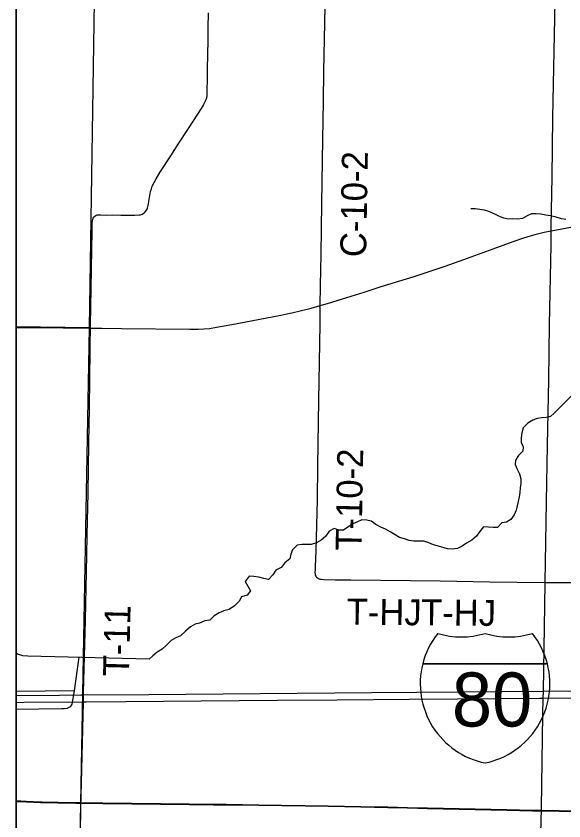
# Model space of a CAD drawing. Extents: x -21.7 to 34, y 0 to 22.
# Drawn here: x 23.517 to 24.718, y 18.47 to 20.235 of the extents above; entities that cross this region are included whole.
import ezdxf

# ---------------------------------------------------------------- set-up
doc = ezdxf.new("R2010")
doc.units = 0
for name, color, linetype in [('Default', 7, 'Continuous'), ('GM_X_County_Road', 7, 'Continuous'), ('GM_X_County_Road_Text', 7, 'Continuous'), ('GM_X_Interchange_Ramps', 7, 'Continuous'), ('GM_X_Interstate_Location', 7, 'Continuous'), ('GM_X_Interstate_Route', 7, 'Continuous'), ('GM_X_Interstate_Shield', 7, 'Continuous'), ('GM_X_Minor_River', 7, 'Continuous'), ('GM_X_Township_Road', 7, 'Continuous'), ('GM_X_Township_Road_Text', 7, 'Continuous'), ('SH_Data', 7, 'Continuous')]:
    doc.layers.add(name, color=color, linetype=linetype)

msp = doc.modelspace()

# ---------------------------------------------------------------- linework, layer by layer
at = {"layer": 'Default'}
for points in [[(23.5167, 20.5562), (23.5167, 19.5535), (23.6774, 19.5512), (23.693, 20.5545)], [(23.5167, 19.5535), (23.5167, 18.5124), (23.6589, 18.509), (23.6774, 19.5512)], [(23.5167, 18.5124), (23.5167, 17.5078), (23.6412, 17.5054), (23.6589, 18.509)]]:
    msp.add_lwpolyline(points, close=True, dxfattribs=at)
at = {"layer": 'GM_X_County_Road'}
for points in [[(24.1832, 19.6003), (24.1843, 19.6442), (24.1852, 19.7126), (24.186, 19.7685), (24.187, 19.8244), (24.1894, 19.9642), (24.1905, 20.0482), (24.1917, 20.1134), (24.194, 20.2563), (24.1969, 20.4303), (24.198, 20.4862), (24.1988, 20.5298), (24.1984, 20.5361), (24.198, 20.5392), (24.1968, 20.5453), (24.1961, 20.5478)], [(24.69, 19.7638), (24.7481, 19.775), (24.8396, 19.793), (24.9068, 19.8058), (24.9313, 19.8101), (24.9391, 19.8111)], [(24.1832, 19.6003), (24.1994, 19.6049), (24.2321, 19.6149), (24.2796, 19.6298), (24.3152, 19.6409), (24.3894, 19.6641), (24.4573, 19.6867), (24.4984, 19.7009), (24.5628, 19.7243), (24.6065, 19.7404), (24.63, 19.7487), (24.6448, 19.7533), (24.6597, 19.7573), (24.6748, 19.7608), (24.69, 19.7638)], [(23.6799, 19.5507), (23.7045, 19.5504), (23.748, 19.5498), (23.8973, 19.5481), (23.916, 19.5481), (23.9284, 19.5488), (23.9408, 19.5502), (23.9562, 19.5526), (23.9899, 19.5587), (24.0938, 19.5786), (24.1212, 19.5842), (24.1394, 19.5884), (24.1635, 19.5946), (24.1832, 19.6003)], [(23.5167, 19.552), (23.5273, 19.552), (23.6205, 19.5512), (23.6799, 19.5507)], [(23.5167, 18.5132), (23.5271, 18.5128), (23.5393, 18.5117), (23.5703, 18.5106), (23.648, 18.5089), (23.6587, 18.5088)], [(23.6418, 17.5061), (23.6446, 17.6719), (23.6457, 17.7465), (23.6483, 17.8864), (23.6502, 17.9827), (23.6521, 18.0884), (23.6541, 18.2189), (23.6576, 18.4334), (23.6587, 18.5088)], [(23.6587, 18.5088), (23.707, 18.5083), (23.8966, 18.5061), (23.9494, 18.5054), (23.9774, 18.5053), (24.0489, 18.5042), (24.2012, 18.5021), (24.2727, 18.5005), (24.3318, 18.4993), (24.3753, 18.4983), (24.4188, 18.4974), (24.5928, 18.4936), (24.6488, 18.4923), (24.6684, 18.492)], [(24.6684, 18.492), (24.7078, 18.4915), (24.7607, 18.491), (24.8167, 18.4905), (24.8475, 18.4904), (24.8561, 18.4908), (24.8648, 18.4904), (24.9765, 18.4895), (25.0106, 18.4897), (25.0261, 18.4894), (25.1038, 18.489), (25.1753, 18.4892), (25.2057, 18.4892), (25.2989, 18.4897), (25.3424, 18.4896), (25.4575, 18.4905), (25.5165, 18.4908), (25.5538, 18.4912), (25.6651, 18.4908)]]:
    msp.add_lwpolyline(points, dxfattribs=at)
at = {"layer": 'GM_X_Interchange_Ramps'}
for points in [[(23.5167, 20.9), (23.5167, 18.5138), (23.5268, 18.5133), (23.5391, 18.5122), (23.5701, 18.5111), (23.6478, 18.5094), (23.6584, 18.5093), (23.7068, 18.5088), (23.8964, 18.5067), (23.9492, 18.506), (23.9772, 18.5058), (24.0487, 18.5048), (24.201, 18.5026), (24.2725, 18.501), (24.3315, 18.4999), (24.375, 18.4989), (24.4186, 18.4979), (24.5926, 18.4941), (24.6486, 18.4929), (24.6682, 18.4926), (24.7076, 18.492), (24.7605, 18.4915)], [(24.7605, 18.4915), (24.7076, 18.492), (24.6682, 18.4926), (24.6486, 18.4929), (24.5926, 18.4941), (24.4186, 18.4979), (24.375, 18.4989), (24.3315, 18.4999), (24.2725, 18.501), (24.201, 18.5026), (24.0487, 18.5048), (23.9772, 18.5058), (23.9492, 18.506), (23.8964, 18.5067), (23.7068, 18.5088), (23.6584, 18.5093), (23.6478, 18.5094), (23.5701, 18.5111), (23.5391, 18.5122), (23.5268, 18.5133), (23.5167, 18.5138), (23.5167, 14.1)]]:
    msp.add_lwpolyline(points, dxfattribs=at)
at = {"layer": 'GM_X_Interstate_Route'}
for points in [[(23.5167, 18.7447), (23.6117, 18.7455), (23.6583, 18.7461), (23.6647, 18.7461), (23.8076, 18.7474), (24.2957, 18.7516), (24.3952, 18.7524), (24.6719, 18.7544), (24.6727, 18.7544), (24.762, 18.7551), (24.795, 18.7556), (24.8364, 18.7559), (25.0478, 18.758), (25.1275, 18.7588), (25.1308, 18.7588), (25.2686, 18.7601), (25.3084, 18.7599), (25.3908, 18.7602)], [(23.5167, 18.7298), (23.5334, 18.73), (23.6643, 18.7311), (23.6702, 18.7312), (23.7573, 18.7318), (23.9221, 18.7333), (24.006, 18.734), (24.09, 18.7346), (24.2205, 18.7354), (24.3791, 18.7368), (24.4848, 18.7376), (24.6641, 18.7391), (24.6725, 18.7391), (24.8182, 18.7401)]]:
    msp.add_lwpolyline(points, dxfattribs=at)
at = {"layer": 'GM_X_Interstate_Shield'}
for p, q in [((24.4083, 18.8146), (24.6815, 18.8146)), ((24.6815, 18.8146), (24.4083, 18.8146)), ((24.6815, 18.8146), (24.4083, 18.8146))]:
    msp.add_line(p, q, dxfattribs=at)
for centre, start, end in [((24.5804, 18.771), 141.669, 165.8066), ((24.493, 19.051), 253.0091, 286.9909), ((24.5968, 19.051), 253.0091, 286.9909), ((24.5094, 18.771), 14.1934, 38.331), ((24.5804, 18.771), 165.8066, 258.463), ((24.5094, 18.771), 281.537, 14.1934)]:
    msp.add_arc(centre, 0.1776, start, end, dxfattribs=at)
at = {"layer": 'GM_X_Minor_River'}
msp.add_line((23.644, 18.7551), (23.5167, 18.7536), dxfattribs=at)
for points in [[(24.7223, 19.789), (24.7125, 19.7907), (24.7008, 19.7937), (24.6884, 19.797), (24.6778, 19.7987), (24.6669, 19.8009), (24.657, 19.8015), (24.6471, 19.8013), (24.6375, 19.7966), (24.6268, 19.7911), (24.6161, 19.7898), (24.6059, 19.7901), (24.596, 19.7899), (24.5858, 19.7917), (24.5753, 19.7964), (24.5648, 19.8016), (24.5532, 19.8068), (24.5434, 19.8097), (24.5332, 19.8107), (24.5229, 19.812), (24.5135, 19.8122), (24.5135, 19.8126)], [(25.1354, 19.3812), (25.0331, 19.3064), (24.9486, 19.423), (24.7737, 19.4409), (24.6964, 19.364), (24.6882, 19.3566), (24.6787, 19.3546), (24.6688, 19.354), (24.6593, 19.3527)], [(24.6593, 19.3527), (24.6494, 19.3488), (24.6386, 19.3422), (24.6285, 19.3318), (24.6259, 19.3208), (24.6242, 19.3102), (24.6239, 19.3004), (24.6282, 19.2904), (24.628, 19.2805), (24.6183, 19.2713), (24.6116, 19.2612), (24.611, 19.2513), (24.6153, 19.2413), (24.6204, 19.231), (24.6232, 19.2203), (24.6237, 19.21), (24.622, 19.2002), (24.6213, 19.1903), (24.6196, 19.1805), (24.6153, 19.1609), (24.6128, 19.1511), (24.6088, 19.1409), (24.6017, 19.1312), (24.5917, 19.1253), (24.5818, 19.1233), (24.5725, 19.1136), (24.5626, 19.1131), (24.5524, 19.1141), (24.5418, 19.1147), (24.5324, 19.1039), (24.5265, 19.0941), (24.5157, 19.0856), (24.5045, 19.0794), (24.4945, 19.0728), (24.4845, 19.0677), (24.4727, 19.0657), (24.4629, 19.0667), (24.4425, 19.0725), (24.432, 19.0757), (24.4218, 19.0801), (24.4109, 19.0834), (24.4003, 19.0833), (24.3885, 19.0832), (24.3787, 19.0849), (24.3685, 19.0882), (24.3572, 19.0918), (24.3475, 19.0977), (24.3366, 19.1041), (24.3265, 19.11), (24.3164, 19.114), (24.3055, 19.1203), (24.2955, 19.127), (24.2856, 19.1295), (24.275, 19.1301), (24.2655, 19.1258), (24.2551, 19.1214), (24.2443, 19.1145), (24.2343, 19.1078), (24.2244, 19.1077), (24.2139, 19.111), (24.2031, 19.1051), (24.1949, 19.0939), (24.1852, 19.0858), (24.1752, 19.0799), (24.1637, 19.0764), (24.1542, 19.0758), (24.1436, 19.0765), (24.1326, 19.0748), (24.1229, 19.0648), (24.1192, 19.055), (24.1167, 19.0444), (24.1059, 19.0359), (24.0981, 19.0258), (24.0862, 19.02), (24.0798, 19.0099), (24.0701, 18.9995), (24.0595, 19.0013), (24.049, 19.0042), (24.038, 19.0059), (24.0274, 19.0065), (24.0192, 18.9953), (24.025, 18.985), (24.0304, 18.9746), (24.023, 18.9649), (24.0108, 18.9614), (24.006, 18.9516), (23.9955, 18.9416), (23.984, 18.9339), (23.9721, 18.9307), (23.9622, 18.9264), (23.951, 18.9198), (23.9413, 18.9105), (23.9306, 18.9085), (23.9191, 18.9038), (23.9096, 18.9014), (23.8988, 18.8955), (23.8884, 18.8859), (23.8771, 18.8759), (23.8668, 18.8712), (23.8568, 18.8653), (23.8463, 18.8557)], [(23.8463, 18.8557), (23.8366, 18.8464), (23.8262, 18.8402), (23.8165, 18.8321), (23.8084, 18.825)], [(23.5422, 18.8313), (23.5316, 18.832), (23.5195, 18.8356), (23.5167, 18.8379)], [(23.654, 18.8287), (23.644, 18.7551), (23.639, 18.7262), (23.6349, 18.72), (23.6282, 18.7162), (23.6223, 18.7158), (23.6161, 18.7154), (23.5167, 18.7142)], [(23.8084, 18.825), (23.5422, 18.8313)]]:
    msp.add_lwpolyline(points, dxfattribs=at)
at = {"layer": 'GM_X_Township_Road'}
for points in [[(24.69, 19.7638), (24.69, 19.7731), (24.6917, 19.882), (24.6937, 20.0126), (24.6988, 20.2673), (24.6995, 20.3171), (24.7004, 20.3606), (24.7013, 20.4166), (24.7021, 20.4508), (24.7034, 20.5441)], [(23.6799, 19.5507), (23.6801, 19.5594), (23.6807, 19.5966), (23.6834, 19.7644), (23.6837, 19.7799), (23.6841, 19.786), (23.6847, 19.7889), (23.6859, 19.7917), (23.6874, 19.7941), (23.6893, 19.7962), (23.6917, 19.7978), (23.6944, 19.7988), (23.6973, 19.7992), (23.7026, 19.7993), (23.715, 19.7987), (23.7274, 19.7989), (23.7461, 19.7987), (23.7554, 19.7987), (23.7771, 19.7987), (23.7865, 19.799), (23.7897, 19.7994), (23.7928, 19.8004), (23.7954, 19.8018), (23.798, 19.8038), (23.8002, 19.8062), (23.8021, 19.8087), (23.8037, 19.8112), (23.8049, 19.814), (23.8058, 19.8168), (23.8065, 19.8198), (23.8099, 19.8412), (23.8116, 19.8503), (23.8132, 19.8562), (23.8153, 19.862), (23.8192, 19.8703), (23.8237, 19.8784), (23.8318, 19.8917), (23.8571, 19.9308), (23.8707, 19.9516), (23.8961, 19.9907), (23.9229, 20.032), (23.9272, 20.0395), (23.9283, 20.0421), (23.9313, 20.0474), (23.9336, 20.052), (23.9348, 20.0555), (23.9356, 20.0609), (23.9359, 20.0678), (23.9358, 20.0786), (23.9362, 20.0901), (23.9362, 20.1088), (23.9372, 20.1602), (23.9377, 20.1726), (23.9378, 20.2008), (23.9377, 20.2094), (23.9387, 20.2422)], [(24.69, 19.7638), (24.7481, 19.775), (24.8396, 19.793), (24.9068, 19.8058), (24.9313, 19.8101), (24.9391, 19.8111)], [(24.1832, 19.6003), (24.1994, 19.6049), (24.2321, 19.6149), (24.2796, 19.6298), (24.3152, 19.6409), (24.3894, 19.6641), (24.4573, 19.6867), (24.4984, 19.7009), (24.5628, 19.7243), (24.6065, 19.7404), (24.63, 19.7487), (24.6448, 19.7533), (24.6597, 19.7573), (24.6748, 19.7608), (24.69, 19.7638)], [(24.6768, 18.9929), (24.6798, 19.1697), (24.6818, 19.2942), (24.6846, 19.4372), (24.6863, 19.5585), (24.6898, 19.7327), (24.69, 19.7638)], [(23.6799, 19.5507), (23.7045, 19.5504), (23.748, 19.5498), (23.8973, 19.5481), (23.916, 19.5481), (23.9284, 19.5488), (23.9408, 19.5502), (23.9562, 19.5526), (23.9899, 19.5587), (24.0938, 19.5786), (24.1212, 19.5842), (24.1394, 19.5884), (24.1635, 19.5946), (24.1832, 19.6003)], [(24.1745, 19.0064), (24.1734, 19.0088), (24.1728, 19.0117), (24.1727, 19.0153), (24.1728, 19.0189), (24.1732, 19.028), (24.1744, 19.0622), (24.1772, 19.1741), (24.1782, 19.2487), (24.1807, 19.3917), (24.1832, 19.5596), (24.1832, 19.5969), (24.1832, 19.6003)], [(23.5167, 19.552), (23.5273, 19.552), (23.6205, 19.5512), (23.6799, 19.5507)], [(23.6587, 18.5088), (23.659, 18.5154), (23.6594, 18.5247), (23.6603, 18.5527), (23.6643, 18.7311), (23.6647, 18.7461), (23.6648, 18.7515), (23.6685, 18.9099), (23.6716, 19.0528), (23.6726, 19.0963), (23.6744, 19.1896), (23.6762, 19.2983), (23.6776, 19.376), (23.6792, 19.5034), (23.6792, 19.5159), (23.6799, 19.5507)], [(24.1745, 19.0064), (24.1756, 19.0043), (24.1774, 19.0027), (24.1796, 19.0013), (24.1824, 19.0003), (24.1853, 18.9998), (24.1914, 18.9993), (24.2162, 18.999), (24.2505, 18.9989), (24.3811, 18.9974), (24.4464, 18.9964), (24.5553, 18.9946), (24.6143, 18.9938), (24.6768, 18.9929)], [(24.6684, 18.492), (24.6685, 18.4981), (24.6718, 18.7033), (24.6725, 18.7391), (24.6727, 18.7544), (24.676, 18.9427), (24.6768, 18.9929)], [(24.6768, 18.9929), (24.6859, 18.9928), (24.7543, 18.9927), (24.8507, 18.9925), (24.9502, 18.9927), (25.0995, 18.9922), (25.1753, 18.992)], [(24.6473, 17.4912), (24.6488, 17.5609), (24.651, 17.6634), (24.6547, 17.8251), (24.6567, 17.9152), (24.6595, 18.0551), (24.6605, 18.1017), (24.6626, 18.2136), (24.6653, 18.3441), (24.6662, 18.3908), (24.6671, 18.4374), (24.6677, 18.4747), (24.6684, 18.492)]]:
    msp.add_lwpolyline(points, dxfattribs=at)
at = {"layer": 'SH_Data'}
msp.add_line((23.5167, 20.9), (23.5167, 14.1), dxfattribs=at)
msp.add_lwpolyline([(23.5167, 20.9), (30.3167, 20.9), (30.3167, 14.1), (23.5167, 14.1)], close=True, dxfattribs=at)

# ---------------------------------------------------------------- texts
at = {"layer": 'GM_X_County_Road_Text'}
msp.add_text('C-10-2', height=0.05682, rotation=89.0259, dxfattribs=at).set_placement((24.2841, 19.7059))
at = {"layer": 'GM_X_Interstate_Location'}
for s in ['-', '.', ',']:
    msp.add_text(s, height=0.000189, dxfattribs=at).set_placement((24.5449, 18.739))
msp.add_text('80', height=0.000189, rotation=0, dxfattribs=at).set_placement((24.5062, 18.6998))
at = {"layer": 'GM_X_Interstate_Shield'}
msp.add_text('80', height=0.11837, dxfattribs=at).set_placement((24.4722, 18.677))
at = {"layer": 'GM_X_Township_Road_Text'}
for s, rotation, p in [('T-10-2', 89.0072, (24.274, 19.0622)), ('T-HJ', 359.2731, (24.2411, 18.9008)), ('T-11', 88.5863, (23.764, 18.7863)), ('T-HJ', 359.329, (24.4042, 18.8994))]:
    msp.add_text(s, height=0.05682, rotation=rotation, dxfattribs=at).set_placement(p)

doc.saveas('drawing.dxf')
